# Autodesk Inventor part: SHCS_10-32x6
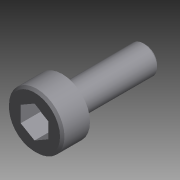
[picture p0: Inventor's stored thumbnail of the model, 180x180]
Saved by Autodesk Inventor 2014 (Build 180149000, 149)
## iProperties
Shininess: 0.0
Length Units: 11272
Angle Units: 11279
Time Units: 11290
Mass Units: 11283
Length Display Precision: 2
Angle Display Precision: 1
Compacted: True
Created: 1999-05
Part Number: SHCS_10-32x6
Document SubType Name: Modeling
Designer: Administrator
Density: 7.84 g/cm^3
Material: Steel, High Strength Low Alloy
Mass: 1.21578 g
Surface Area: 2.42207 cm^2
Volume: 0.155074 cm^3
Appearance: Metal - Steel
Density: 0.0
Volumn: 0.0
Area: 0.0
PropertySet Name: Model Information
Control State: 0
Master: False
Checked Out: False
Author: Administrator
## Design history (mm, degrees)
node "y-z Plane"
  node "x-z Plane"
  node "x-y Plane"
node "Extrusion1" dims "d1" = 3.175, "d2" = 0
  sketch "Sketch1"
    geometry: C1 r 3.175 at (0, 0); 1 further point
    constraints: 1 centre point, 1 coincident
    dimensions: "d0" = 6.35 diameter of C1
node "Chamfer1" dims "d3" = 0.254, "d4" = 0.254, "d18" = 45 deg
node "Extrusion3" dims "d10" = 9.525, "d11" = 0
  sketch "Sketch3"
    geometry: C1 r 3.175 at (0, 0) reference; C2 r 1.587 at (0, 0)
    constraints: 1 centre point
    dimensions: "d9" = 3.175 diameter of C2
node "Chamfer2" dims "d12" = 0.254, "d13" = 0.254, "d19" = 45 deg
node "Extrusion4" dims "d16" = 2.286, "d17" = 0
  sketch "Sketch4"
    geometry: L1 (0, 4.445)-(0, -4.445) reference; L2 (-4.445, 0)-(4.445, 0) reference; L3 (0, 1.833)-(-1.588, 0.917); L4 (-1.588, 0.917)-(-1.588, -0.917); L5 (-1.588, -0.917)-(0, -1.833); L6 (0, -1.833)-(1.588, -0.917); L7 (1.588, -0.917)-(1.588, 0.917); L8 (1.588, 0.917)-(0, 1.833); C1 r 2.921 at (0, 0) reference; A1 r 1.833 centre (0, 0) between (0, 1.833) and (-1.588, 0.917)
    constraints: 12 end point, 6 point on circle, 3 parallel, 2 point on line, 1 centre point, 1 coincident, 1 perpendicular
    dimensions: "d14" = 120 deg angle of L8 L3; "d15" = 3.175 distance between parallel lines of L6 L3
body "Solid1"
